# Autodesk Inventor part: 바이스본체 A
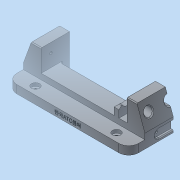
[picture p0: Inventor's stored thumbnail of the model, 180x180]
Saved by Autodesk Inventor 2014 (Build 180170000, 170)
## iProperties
Created: 2017-04
Part Number: 바이스본체 A
Material: 알루미늄 6061
Document SubType Name: Modeling
Designer: mduedu
Density: 2.71 g/cm^3
Appearance: 기본값
Mass: 324.154 g
Surface Area: 276.938 cm^2
Volume: 119.614 cm^3
Author: mduedu
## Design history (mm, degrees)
sketch "스케치1"
  geometry: L1 (-75, 0)-(75, 0); L2 (-75, 0)-(-75, 17); L3 (-53, 17)-(53, 17); L4 (75, 17)-(75, 0); L5 (-75, 17)-(-65.173, 44); L6 (-65.173, 44)-(-53, 44); L7 (-53, 44)-(-53, 17); L8 (0, 0)-(0, 17); L9 (75, 17)-(65.173, 44); L10 (65.173, 44)-(53, 44); L11 (53, 44)-(53, 17); 1 further point
  constraints: 22 end point, 4 perpendicular, 2 horizontal alignment, 2 midpoint, 2 symmetric about line, 1 coincident, 1 collinear, 1 horizontal, 1 vertical
  dimensions: "d0" = 150 distance of L1.start L1.end; "d1" = 17 distance of L1.start L2.end; "d2" = 27 distance of L3.start L6.end; "d3" = 22 distance of L3.start L2.end; "d4" = 70 deg angle of L3 L5; "d54" = 20 deg angle of L9 L4
extrude "돌출1" new body sketch "스케치1" stored distance "d5" = 70; taper "d6" = 0 deg
sketch "스케치2"
  geometry: L1 (0, 70)-(106, 70) reference; L2 (106, 70)-(106, 0) reference; L3 (106, 0)-(0, 0) reference; L4 (0, 47)-(106, 47); L5 (106, 47)-(106, 23); L6 (106, 23)-(0, 23); L7 (0, 23)-(0, 47); L8 (0, 70)-(0, 0) reference; 2 further points
  constraints: 8 end point, 2 parallel, 2 point on line, 1 horizontal, 1 horizontal alignment, 1 midpoint, 1 perpendicular
  dimensions: "d7" = 24 distance between parallel lines of L6 L4
extrude "돌출2" cut sketch "스케치2" stored distance "d9" = 70; taper "d10" = 0 deg
sketch "스케치3"
  geometry: L1 (22, -23)-(128, -23) reference; L2 (128, -47)-(22, -47) reference; L3 (22, -18)-(128, -18); L4 (128, -52)-(22, -52); L5 (22, -18)-(22, -52); L6 (128, -18)-(128, -52); 1 further point
  constraints: 8 end point, 3 parallel, 2 point on line, 1 perpendicular
  dimensions: "d11" = 5 distance between parallel lines of L3 L1; "d12" = 5 distance between parallel lines of L4 L2
extrude "돌출3" cut sketch "스케치3" distance "d13" = 12; taper "d14" = 0 deg
fillet "모깎기1" dims "d15" = 3, "d16" = 3
sketch "스케치4"
  geometry: L1 (103, 23)-(3, 23) reference; L2 (0, 26)-(0, 0) reference; L3 (106, 0)-(0, 0) reference; L4 (106, 26)-(106, 0) reference; L5 (96, 0)-(90, 0); L6 (90, 0)-(90, 19.5); L7 (96, 19.5)-(96, 0); L8 (90, 19.5)-(96, 19.5); A1 r 3 centre (3, 26) between (0, 26) and (3, 23) reference; A2 r 3 centre (103, 26) between (103, 23) and (106, 26) reference; 1 further point
  constraints: 8 end point, 2 perpendicular, 1 horizontal, 1 parallel, 1 point on line
  dimensions: "d17" = 10 distance between parallel lines of L7 L4; "d18" = 6 distance between parallel lines of L7 L6; "d27" = 3.5 distance between parallel lines of L8 L1
extrude "돌출4" join sketch "스케치4" distance "d19" = 12; taper "d20" = 0 deg
chamfer "모따기1" distance "d21" = 3; stored, may be unused: second distance "d22" = 2, angle "d23" = 45 deg
chamfer "모따기2" distance "d24" = 3; stored, may be unused: second distance "d25" = 2, angle "d26" = 45 deg
sketch "스케치5"
  geometry: L1 (-15.5, 35.8)-(-15.5, -25.8) reference; L2 (19.5, 0)-(0, 0) reference; C1 r 6.5 at (9.5, 15); 1 further point
  constraints: 1 centre point
  dimensions: "d28" = 13 diameter of C1; "d30" = 15 distance from line of C1.centre L2; "d31" = 25 distance from line of C1.centre L1
extrude "돌출5" cut sketch "스케치5" stored distance "d32" = 12; taper "d33" = 0 deg
sketch "스케치6"
  geometry: C1 r 5 at (-10, 15); C2 r 5 at (-60, 15); A1 r 6.5 centre (-10, 15) between (-15.766, 12) and (-4.234, 12) reference; A2 r 6.5 centre (-60, 15) between (-65.766, 12) and (-54.234, 12) reference; 1 further point
  constraints: 2 centre point, 2 coincident
  dimensions: "d34" = 10 diameter of C1; "d35" = 10 diameter of C2 (= d34)
extrude "돌출6" cut sketch "스케치6" stored distance "d36" = 12; taper "d37" = 0 deg
chamfer "모따기3" distance "d38" = 1; stored, may be unused: second distance "d39" = 2, angle "d40" = 45 deg
chamfer "모따기4" distance "d41" = 1; stored, may be unused: second distance "d42" = 2, angle "d43" = 45 deg
sketch "스케치7"
  geometry: L1 (-35, 35.8)-(-35, -25.8) reference; L2 (-70, 0)-(0, 0) reference; C1 r 5 at (-35, 15); 1 further point
  constraints: 1 centre point, 1 point on line
  dimensions: "d44" = 10 diameter of C1; "d45" = 15 distance from line of C1.centre L2
extrude "돌출7" cut sketch "스케치7" stored distance "d46" = 12; taper "d47" = 0 deg
chamfer "모따기5" distance "d48" = 1; stored, may be unused: second distance "d49" = 2, angle "d50" = 45 deg
node "작업축1"
sketch "스케치8"
  geometry: L1 (-105, 32)-(105, 32) reference; L2 (58, 32)-(64, 32); L3 (64, 32)-(64, 40); L4 (64, 40)-(58, 40); L5 (58, 40)-(58, 32); L6 (53, 38)-(53, 26) reference; 1 further point
  constraints: 8 end point, 2 parallel, 1 horizontal, 1 perpendicular, 1 point on line
  dimensions: "d51" = 5 distance from line of L6 L2.start; "d52" = 6 distance of L3.end L4.end; "d53" = 16 diameter of L4 L1
revolve "회전1" sketch "스케치8" stored, may be unused: angle "d55" = 90 deg
fillet "모깎기2"
chamfer "모따기6" distance "d56" = 1; stored, may be unused: second distance "d57" = 2, angle "d58" = 45 deg
sketch "스케치9"
  geometry: L1 (17.5, 3)-(52.5, 3); L2 (52.5, 13)-(17.5, 13); L3 (70, 0)-(0, 0) reference; L4 (17.5, 8)-(52.5, 8); A1 r 5 centre (17.5, 8) between (17.5, 13) and (17.5, 3); A2 r 5 centre (52.5, 8) between (52.5, 3) and (52.5, 13); 3 further points
  constraints: 6 end point, 4 point on circle, 3 tangent, 2 centre point, 2 midpoint, 2 parallel, 1 horizontal, 1 vertical alignment
  dimensions: "d59" = 35 distance of L4.start L4.end; "d61" = 5 radius of A2; "d62" = 8 distance between parallel lines of L3 L4
extrude "돌출8" cut sketch "스케치9" distance "d63" = 3; taper "d64" = 0 deg
chamfer "모따기7" distance "d65" = 1; stored, may be unused: second distance "d66" = 2, angle "d67" = 45 deg
chamfer "모따기8" distance "d68" = 1; stored, may be unused: second distance "d69" = 2, angle "d70" = 45 deg
feature "분할1"
sketch "스케치10"
  geometry: L1 (35, 27)-(0, 27) reference; L2 (0, 0)-(0, 27) reference; 1 further point
  dimensions: "d85" = 11.5 distance from line of point (12, 15.5) L1; "d86" = 12 distance from line of point (12, 15.5) L2
hole "구멍1" sketch "스케치10" at (12, 15.5) diameter "d71" = 3.242; stored, may be unused: countersink angle "d75" = 90 deg, drill point angle "d77" = 120 deg; dims "d72" = 8, "d73" = 4, "d74" = 2, "d76" = 10
sketch "스케치11"
  geometry: A1 r 5 centre (17.5, 8) between (17.5, 13) and (17.5, 3) reference; 1 further point
  constraints: 1 coincident
hole "구멍3" sketch "스케치11" at (17.5, 8) diameter "d78" = 2.459; stored, may be unused: countersink angle "d82" = 90 deg, drill point angle "d84" = 120 deg; dims "d79" = 4.5, "d80" = 4, "d81" = 2, "d83" = 6
sketch "스케치13"
  geometry: L1 (75, 0)-(75, 35) reference; L2 (-75, 0)-(-75, 35) reference; L3 (-75, 35)-(75, 35); L4 (75, 35)-(75, 55); L5 (75, 55)-(-75, 55); L6 (-75, 55)-(-75, 35); 1 further point
  constraints: 8 end point, 2 parallel, 1 horizontal, 1 perpendicular, 1 point on line
  dimensions: "d90" = 20 distance between parallel lines of L5 L3; "d94" = 150 distance of L4.end L5.end (derived)
extrude "돌출9" join sketch "스케치13" distance "d92" = 10; taper "d93" = 0 deg
sketch "스케치14"
  geometry: L1 (-75, -35)-(-75, -55) reference; L2 (75, -55)-(75, -35) reference; L3 (-75, -45)-(75, -45); 3 further points
  constraints: 2 end point, 2 midpoint, 2 point on line
  dimensions: "d95" = 50 horizontal distance of point (-50, -45) point (0, 0); "d96" = 100 distance of point (50, -45) point (-50, -45)
fillet "모깎기3" dims "d97" = 12
chamfer "모따기9" distance "d98" = 1; stored, may be unused: second distance "d99" = 2, angle "d100" = 45 deg
hole "구멍4" sketch "스케치14" diameter "d101" = 4.134; stored, may be unused: countersink angle "d105" = 90 deg, drill point angle "d107" = 118 deg; dims "d102" = 6, "d103" = 10, "d104" = 4, "d106" = 8
sketch "스케치15"
  geometry: L1 (0, 0)-(126, 0) reference; 3 further points
  constraints: 1 midpoint, 1 vertical alignment, 1 other
  dimensions: "d109" = 5 distance from line of point (63, 5) L1
feature "엠보싱2" sketch "스케치15" dims "d0" = 150, "d1" = 17, "d2" = 27, "d3" = 22, "d4" = 70 deg, "d54" = 20 deg, "d110" = 0.5, "d111" = 0
node "솔리드1"
mirror "대칭1"
mirror "대칭2"
mirror "대칭3"
mirror "대칭4"
node "투영된 루프1"
